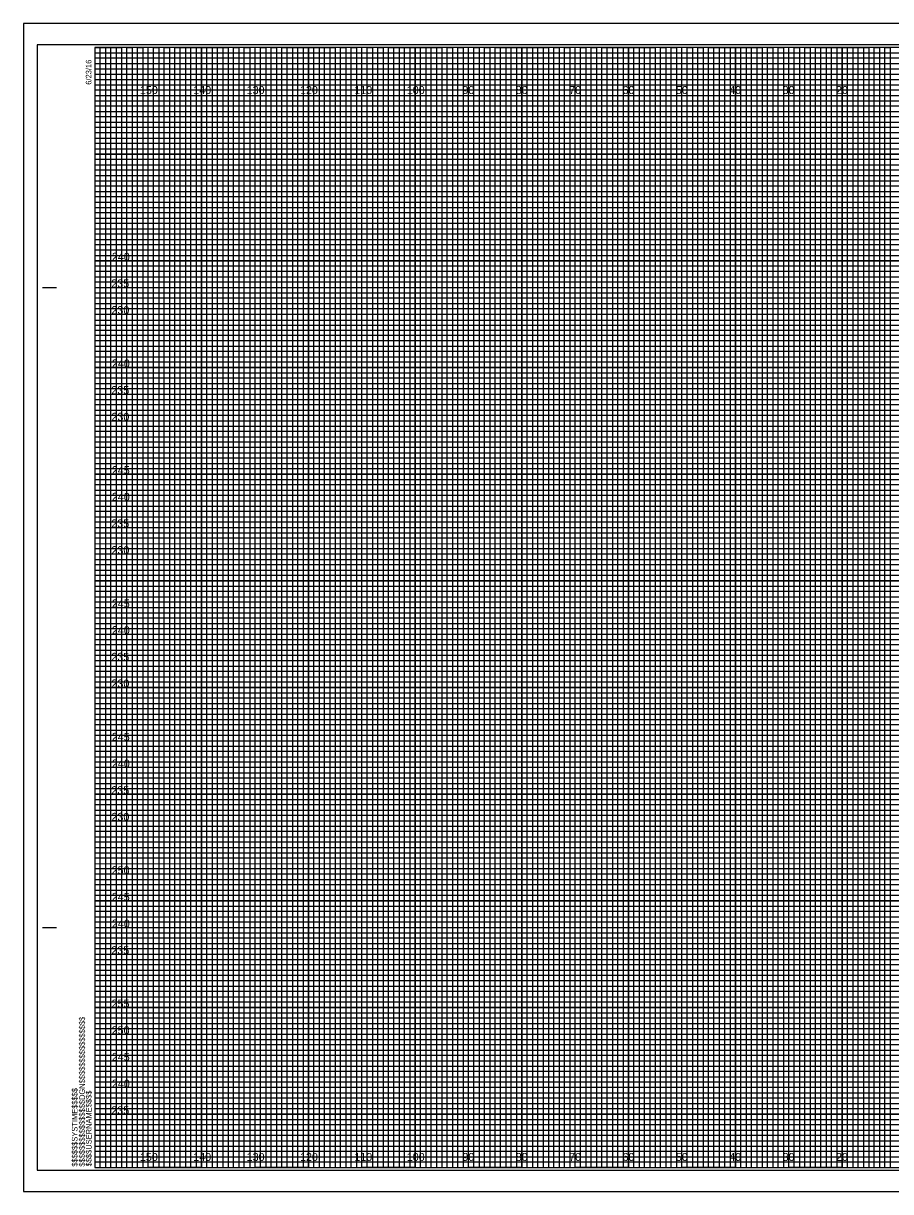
# Model space of a CAD drawing. Extents: x -13 to 323, y -5 to 215.
# Drawn here: x -13.4 to 149.1, y -4.5 to 214.5 of the extents above; entities that cross this region are included whole.
import ezdxf

# ---------------------------------------------------------------- set-up
doc = ezdxf.new("R2010")
doc.units = 0
for name, color, linetype in [('Exist CMT Pavement', 7, 'Continuous'), ('Exist Cross Section Cell', 7, 'Continuous'), ('Exist XS Center Line Elevation Label', 7, 'Continuous'), ('Exist XS Ground Line', 7, 'Continuous'), ('Prop CMT Concrete Structures', 7, 'Continuous'), ('Prop CMT Pvmt Course 2', 7, 'Continuous'), ('Prop CMT Pvmt Course 2 Wedge', 7, 'Continuous'), ('Prop CMT Pvmt Course 3', 7, 'Continuous'), ('Prop CMT Pvmt Course 3 Wedge', 7, 'Continuous'), ('Prop CMT Pvmt Surface', 7, 'Continuous'), ('Prop CMT Subgrade Earthwork', 7, 'Continuous')]:
    doc.layers.add(name, color=color, linetype=linetype)

msp = doc.modelspace()

# ---------------------------------------------------------------- linework, layer by layer
at = {"layer": 'Exist CMT Pavement'}
for p, q in [((323.3, 214.5), (-13.4, 214.5)), ((-13.4, 214.5), (-13.4, -4.5)), ((-13.4, -4.5), (323.3, -4.5))]:
    msp.add_line(p, q, dxfattribs=at)
at = {"layer": 'Exist XS Center Line Elevation Label'}
for points in [[(0, 210), (5, 210), (5, 0), (15, 0), (15, 210), (25, 210), (25, 0), (35, 0), (35, 210), (45, 210), (45, 0), (55, 0), (55, 210), (65, 210), (65, 0), (75, 0), (75, 210), (85, 210), (85, 0), (95, 0), (95, 210), (105, 210), (105, 0), (115, 0), (115, 210), (125, 210), (125, 0), (135, 0), (135, 210), (145, 210), (145, 0), (155, 0)], [(0, 205), (275, 205)], [(0, 185), (320, 185), (320, 195), (0, 195)], [(0, 165), (320, 165), (320, 175), (0, 175)], [(0, 145), (320, 145), (320, 155), (0, 155)], [(0, 125), (320, 125), (320, 135), (0, 135)], [(0, 105), (320, 105), (320, 115), (0, 115)], [(0, 85), (320, 85), (320, 95), (0, 95)], [(0, 65), (320, 65), (320, 75), (0, 75)], [(0, 45), (320, 45), (320, 55), (0, 55)], [(0, 25), (320, 25), (320, 35), (0, 35)], [(0, 5), (320, 5), (320, 15), (0, 15)]]:
    msp.add_lwpolyline(points, dxfattribs=at)
at = {"layer": 'Exist XS Ground Line'}
for p, q in [((10, 210), (0, 210)), ((10, 0), (10, 210)), ((30, 210), (20, 210)), ((20, 210), (20, 0)), ((30, 0), (30, 210)), ((50, 210), (40, 210)), ((40, 210), (40, 0)), ((50, 0), (50, 210)), ((70, 210), (60, 210)), ((60, 210), (60, 0)), ((70, 0), (70, 210)), ((90, 210), (80, 210)), ((80, 210), (80, 0)), ((90, 0), (90, 210)), ((110, 210), (100, 210)), ((100, 210), (100, 0)), ((110, 0), (110, 210)), ((130, 210), (120, 210)), ((120, 210), (120, 0)), ((130, 0), (130, 210)), ((150, 210), (140, 210)), ((140, 210), (140, 0)), ((20, 0), (10, 0)), ((40, 0), (30, 0)), ((60, 0), (50, 0)), ((80, 0), (70, 0)), ((100, 0), (90, 0)), ((120, 0), (110, 0)), ((140, 0), (130, 0))]:
    msp.add_line(p, q, dxfattribs=at)
for points in [[(0, 200), (320, 200), (320, 190), (0, 190)], [(0, 180), (320, 180), (320, 170), (0, 170)], [(0, 160), (320, 160), (320, 150), (0, 150)], [(0, 140), (320, 140), (320, 130), (0, 130)], [(0, 120), (320, 120), (320, 110), (0, 110)], [(0, 100), (320, 100), (320, 90), (0, 90)], [(0, 80), (320, 80), (320, 70), (0, 70)], [(0, 60), (320, 60), (320, 50), (0, 50)], [(0, 40), (320, 40), (320, 30), (0, 30)], [(0, 20), (320, 20), (320, 10), (0, 10)]]:
    msp.add_lwpolyline(points, dxfattribs=at)
at = {"layer": 'Prop CMT Concrete Structures'}
for p, q in [((10, 0), (10, 210)), ((20, 0), (20, 210)), ((30, 0), (30, 210)), ((40, 0), (40, 210)), ((50, 0), (50, 210)), ((60, 0), (60, 210)), ((70, 0), (70, 210)), ((80, 0), (80, 210)), ((90, 0), (90, 210)), ((100, 0), (100, 210)), ((110, 0), (110, 210)), ((120, 0), (120, 210)), ((130, 0), (130, 210)), ((140, 0), (140, 210)), ((0, 200), (320, 200)), ((0, 190), (320, 190)), ((0, 180), (320, 180)), ((0, 170), (320, 170)), ((0, 160), (320, 160)), ((0, 150), (320, 150)), ((0, 140), (320, 140)), ((0, 130), (320, 130)), ((0, 120), (320, 120)), ((0, 110), (320, 110)), ((0, 100), (320, 100)), ((0, 90), (320, 90)), ((0, 80), (320, 80)), ((0, 70), (320, 70)), ((0, 60), (320, 60)), ((0, 50), (320, 50)), ((0, 40), (320, 40)), ((0, 30), (320, 30)), ((0, 20), (320, 20)), ((0, 10), (320, 10))]:
    msp.add_line(p, q, dxfattribs=at)
at = {"layer": 'Prop CMT Pvmt Course 2'}
for p, q in [((0, 209), (260, 209)), ((260, 207.98), (0, 207.98)), ((0, 207.98), (0, 207)), ((0, 207), (260, 207)), ((260, 205.89), (0, 205.89)), ((0, 205.89), (0, 204)), ((0, 204), (320, 204))]:
    msp.add_line(p, q, dxfattribs=at)
for points in [[(0, 203), (270, 203), (320, 203), (320, 202), (0, 202)], [(0, 201), (320, 201), (320, 199), (0, 199)], [(0, 198), (320, 198), (320, 197), (0, 196.98)], [(0, 196), (320, 196), (320, 194), (0, 194)], [(0, 193), (320, 193), (320, 192), (0, 192)], [(0, 191), (320, 191), (320, 189), (0, 189)], [(0, 188), (320, 188), (320, 187), (0, 187)], [(0, 186), (320, 186), (320, 184), (0, 184)], [(0, 183), (320, 183), (320, 182), (0, 182)], [(0, 181), (320, 181), (320, 179), (0, 179)], [(0, 178), (320, 178), (320, 177), (0, 177)], [(0, 176), (320, 176), (320, 173.95), (320, 173), (320, 172), (0, 172)], [(0, 174), (320, 174), (320, 173), (0, 173)], [(0, 171), (320, 171), (320, 169), (0, 169.03)], [(0, 169.03), (320, 169), (320, 168), (0, 168)], [(0, 167), (320, 167), (320, 166), (0, 166)], [(0, 164), (320, 164), (320, 163), (0, 163)], [(0, 162), (320, 162), (320, 161), (0, 161)], [(-0.07, 158.89), (320, 158.89), (320, 157.88), (-0.07, 157.88)], [(0, 157), (320, 157), (320, 156), (0, 156)], [(0, 154), (320, 154), (320, 153), (0, 153)], [(0, 152), (320, 152), (320, 151), (0, 151)], [(0, 149), (320, 149), (320, 148), (0, 148)], [(0, 147), (320, 147), (320, 146), (0, 146)], [(0, 144), (320, 144), (320, 143), (0, 143)], [(0, 142), (320, 142), (320, 141), (0, 141)], [(0, 139), (320, 139), (319.99, 137.98), (0, 138)], [(0, 137), (320, 137), (320, 136), (0, 136)], [(0, 134), (320, 134), (320, 133), (0, 133)], [(0, 132), (320, 132), (320, 131), (0, 131)], [(0, 129), (320, 129), (320, 128), (0, 128)], [(0, 127), (320, 127), (320, 126), (0, 126)], [(0, 124), (320, 124), (320, 123), (0, 123)], [(0, 122), (320, 122), (320, 121), (0, 121)], [(0, 119), (320, 119), (320, 118), (0, 118)], [(0, 116.99), (320.07, 116.91), (320, 116), (0, 116)], [(0, 114), (320, 114), (320, 113), (0, 113)], [(0, 112), (320, 112), (320, 111), (0, 111)], [(0, 109), (320, 109), (320, 108), (0, 108)], [(0, 107), (320, 107), (320, 106), (0, 106)], [(0, 104), (320, 104), (320, 103), (0, 103)], [(0, 102), (320, 102), (320, 101), (0, 101)], [(0, 99), (320, 99), (320, 98), (0, 98)], [(0, 97), (320, 97), (320, 96), (0, 96)], [(0, 94), (320, 94), (320, 93), (0, 93)], [(0, 92), (320, 92), (320, 91), (0, 91)], [(0, 89), (320, 89), (320, 88), (0, 88)], [(0, 87), (320, 87), (320, 86), (0, 86)], [(0, 84), (320, 84), (320, 83), (0, 83)], [(0, 82), (320, 82), (320, 81), (0, 81)], [(0, 79), (320, 79), (319.99, 77.98), (0, 78)], [(0, 77), (320, 77), (320, 76), (0, 76)], [(0, 74), (320, 74), (320, 73), (0, 73)], [(0, 72), (320, 72), (320, 71), (0, 71)], [(0, 69), (320, 69), (320, 68), (0, 68)], [(0, 67), (320, 67), (320, 66), (0, 66)], [(0, 64), (320, 64), (320, 63), (0, 63)], [(0, 62), (320, 62), (320, 61), (0, 61)], [(0, 59), (320, 59), (320, 58), (0, 58)], [(0, 56.99), (320.07, 56.91), (320, 56), (0, 56)], [(0, 54), (320, 54), (320, 53), (0, 53)], [(0, 52), (320, 52), (320, 51), (0, 51)], [(0, 49), (320, 49), (320, 48), (0, 48)], [(0, 47), (320, 47), (320, 46), (0, 46)], [(0, 44), (320, 44), (320, 43), (0, 43)], [(0, 42), (320, 42), (320, 41), (0, 41)], [(0, 39), (320, 39), (320, 38), (0, 38)], [(0, 37), (320, 37), (320, 36), (0, 36)], [(0, 34), (320, 34), (320, 33), (0, 33)], [(0, 32), (320, 32), (320, 31), (0, 31)], [(0, 29), (320, 29), (320, 28), (0, 28)], [(0, 27), (320, 27), (320, 26), (0, 26)], [(0, 24), (320, 24), (320, 23), (0, 23)], [(0, 22), (320, 22), (320, 21), (0, 21)], [(0, 19), (320, 19), (320, 18), (0, 18)], [(0, 17), (320, 17), (320, 16), (0, 16)], [(0, 14), (320, 14), (320, 13), (0, 13)], [(0, 12), (320, 12), (320, 11), (0, 11)], [(0, 9), (320, 9), (320, 8), (0, 8)], [(0, 7), (320, 7), (320, 6), (0, 6)], [(0, 4), (320, 4), (320, 3), (0, 3)], [(0, 2), (320, 2), (320, 1), (0, 1)]]:
    msp.add_lwpolyline(points, dxfattribs=at)
at = {"layer": 'Prop CMT Pvmt Course 2 Wedge'}
msp.add_lwpolyline([(-13.4, -4.5), (323.3, -4.5), (323.3, 214.5), (-13.4, 214.5)], close=True, dxfattribs=at)
at = {"layer": 'Prop CMT Pvmt Course 3'}
for p, q in [((-9.8, 165), (-7.3, 165)), ((-9.7, 165), (-7.2, 165)), ((-9.8, 45), (-7.3, 45)), ((-9.7, 45), (-7.2, 45)), ((0, 0), (0, 0)), ((0, 0), (0, 0)), ((0, 0), (0, 0)), ((0, 0), (0, 0)), ((0, 0), (0, 0)), ((0, 0), (0, 0)), ((0, 0), (0, 0))]:
    msp.add_line(p, q, dxfattribs=at)
msp.add_lwpolyline([(320, 210), (0, 210), (0, 0), (320, 0)], close=True, dxfattribs=at)
at = {"layer": 'Prop CMT Pvmt Course 3 Wedge'}
msp.add_lwpolyline([(-10.8, -0.5), (322.4, -0.5), (322.4, 210.5), (-10.8, 210.5)], close=True, dxfattribs=at)
at = {"layer": 'Prop CMT Subgrade Earthwork'}
for points in [[(0, 0), (1, 0), (1, 210), (2, 210), (2, 0)], [(2, 0), (3, 0), (3, 210), (4, 210), (4, 0)], [(5, 0), (6, 0), (6, 210), (7, 210), (7, 0)], [(7, 0), (8, 0), (8, 210), (9, 210), (9, 0)], [(10, 0), (11, 0), (11, 210), (12, 210), (12, 0)], [(12, 0), (13, 0), (13, 210), (14, 210), (14, 0)], [(15, 0), (16, 0), (16, 210), (17, 210), (17, 0)], [(17, 0), (18, 0), (18, 210), (19, 210), (19, 0)], [(20, 0), (21, 0), (21, 210), (22, 210), (22, 0)], [(22, 0), (23, 0), (23, 210), (24, 210), (24, 0)], [(25, 0), (26, 0), (26, 210), (27, 210), (27, 0)], [(27, 0), (28, 0), (28, 210), (29, 210), (29, 0)], [(30, 0), (31, 0), (31, 210), (32, 210), (32, 0)], [(32, 0), (33, 0), (33, 210), (34, 210), (34, 0)], [(35, 0), (36, 0), (36, 210), (37, 210), (37, 0)], [(37, 0), (38, 0), (38, 210), (39, 210), (39, 0)], [(40, 0), (41, 0), (41, 210), (42, 210), (42, 0)], [(42, 0), (43, 0), (43, 210), (44, 210), (44, 0)], [(45, 0), (46, 0), (46, 210), (47, 210), (47, 0)], [(47, 0), (48, 0), (48, 210), (49, 210), (49, 0)], [(50, 0), (51, 0), (51, 210), (52, 210), (52, 0)], [(52, 0), (53, 0), (53, 210), (54, 210), (54, 0)], [(55, 0), (56, 0), (56, 210), (57, 210), (57, 0)], [(57, 0), (58, 0), (58, 210), (59, 210), (59, 0)], [(60, 0), (61, 0), (61, 210), (62, 210), (62, 0)], [(62, 0), (63, 0), (63, 210), (64, 210), (64, 0)], [(65, 0), (66, 0), (66, 210), (67, 210), (67, 0)], [(67, 0), (68, 0), (68, 210), (69, 210), (69, 0)], [(70, 0), (71, 0), (71, 210), (72, 210), (72, 0)], [(72, 0), (73, 0), (73, 210), (74, 210), (74, 0)], [(75, 0), (76, 0), (76, 210), (77, 210), (77, 0)], [(77, 0), (78, 0), (78, 210), (79, 210), (79, 0)], [(80, 0), (81, 0), (81, 210), (82, 210), (82, 0)], [(82, 0), (83, 0), (83, 210), (84, 210), (84, 0)], [(85, 0), (86, 0), (86, 210), (87, 210), (87, 0)], [(87, 0), (88, 0), (88, 210), (89, 210), (89, 0)], [(90, 0), (91, 0), (91, 210), (92, 210), (92, 0)], [(92, 0), (93, 0), (93, 210), (94, 210), (94, 0)], [(95, 0), (96, 0), (96, 210), (97, 210), (97, 0)], [(97, 0), (98, 0), (98, 210), (99, 210), (99, 0)], [(100, 0), (101, 0), (101, 210), (102, 210), (102, 0)], [(102, 0), (103, 0), (103, 210), (104, 210), (104, 0)], [(105, 0), (106, 0), (106, 210), (107, 210), (107, 0)], [(107, 0), (108, 0), (108, 210), (109, 210), (109, 0)], [(110, 0), (111, 0), (111, 210), (112, 210), (112, 0)], [(112, 0), (113, 0), (113, 210), (114, 210), (114, 0)], [(115, 0), (116, 0), (116, 210), (117, 210), (117, 0)], [(117, 0), (118, 0), (118, 210), (119, 210), (119, 0)], [(120, 0), (121, 0), (121, 210), (122, 210), (122, 0)], [(122, 0), (123, 0), (123, 210), (124, 210), (124, 0)], [(125, 0), (126, 0), (126, 210), (127, 210), (127, 0)], [(127, 0), (128, 0), (128, 210), (129, 210), (129, 0)], [(130, 0), (131, 0), (131, 210), (132, 210), (132, 0)], [(132, 0), (133, 0), (133, 210), (134, 210), (134, 0)], [(135, 0), (136, 0), (136, 210), (137, 210), (137, 0)], [(137, 0), (138, 0), (138, 210), (139, 210), (139, 0)], [(140, 0), (141, 0), (141, 210), (142, 210), (142, 0)], [(142, 0), (143, 0), (143, 210), (144, 210), (144, 0)], [(145, 0), (146, 0), (146, 210), (147, 210), (147, 0)], [(147, 0), (148, 0), (148, 210), (149, 210), (149, 0)]]:
    msp.add_lwpolyline(points, dxfattribs=at)

# ---------------------------------------------------------------- texts
at = {"layer": 'Exist Cross Section Cell'}
for s, p in [('150', (8.44, 201.25)), ('140', (18.44, 201.25)), ('130', (28.44, 201.25)), ('120', (38.44, 201.25)), ('110', (48.62, 201.25)), ('100', (58.44, 201.25)), ('90', (68.86, 201.25)), ('80', (78.86, 201.25)), ('70', (88.86, 201.25)), ('60', (98.86, 201.25)), ('50', (108.86, 201.25)), ('40', (118.86, 201.25)), ('30', (128.86, 201.25)), ('20', (138.86, 201.25)), ('150', (8.44, 1.25)), ('140', (18.44, 1.25)), ('130', (28.44, 1.25)), ('120', (38.44, 1.25)), ('110', (48.62, 1.25)), ('100', (58.44, 1.25)), ('90', (68.86, 1.25)), ('80', (78.86, 1.25)), ('70', (88.86, 1.25)), ('60', (98.86, 1.25)), ('50', (108.86, 1.25)), ('40', (118.86, 1.25)), ('30', (128.86, 1.25)), ('20', (138.86, 1.25))]:
    msp.add_text(s, height=1.5, dxfattribs=at).set_placement(p)
at = {"layer": 'Prop CMT Pvmt Course 3'}
for s, p in [('6/23/16', (-0.65, 203)), ('$$$$$$$$$$$$$$$$DGN$$$$$$$$$$$$$$$$', (-1.88, 0.18)), ('$$$$$$SYSTIME$$$$$', (-3.26, 0.18)), ('$$$$USERNAME$$$$', (-0.62, 0.23))]:
    msp.add_text(s, height=1.05, rotation=90, dxfattribs=at).set_placement(p)
at = {"layer": 'Prop CMT Pvmt Surface'}
for s, p in [('240', (3.19, 170)), ('235', (3.09, 165)), ('230', (3.11, 160)), ('240', (3.19, 150)), ('235', (3.09, 145)), ('230', (3.11, 140)), ('245', (3.18, 130)), ('240', (3.19, 125)), ('235', (3.09, 120)), ('230', (3.11, 115)), ('245', (3.18, 105)), ('240', (3.19, 100)), ('235', (3.09, 95)), ('230', (3.11, 90)), ('245', (3.18, 80)), ('240', (3.19, 75)), ('235', (3.09, 70)), ('230', (3.11, 65)), ('250', (3.15, 55)), ('245', (3.18, 50)), ('240', (3.19, 45)), ('235', (3.09, 40)), ('255', (3.13, 30)), ('250', (3.15, 25)), ('245', (3.18, 20)), ('240', (3.19, 15)), ('235', (3.09, 10))]:
    msp.add_text(s, height=1.5, dxfattribs=at).set_placement(p)

doc.saveas('drawing.dxf')
